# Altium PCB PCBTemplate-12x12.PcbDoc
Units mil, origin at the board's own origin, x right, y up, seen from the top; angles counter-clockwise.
Board outline 12000 x 12000 mil, 4 copper layers (Top Layer, Internal Plane 1, Internal Plane 2, Bottom Layer); 0 components, 0 nets, 1 pads, 0 vias.
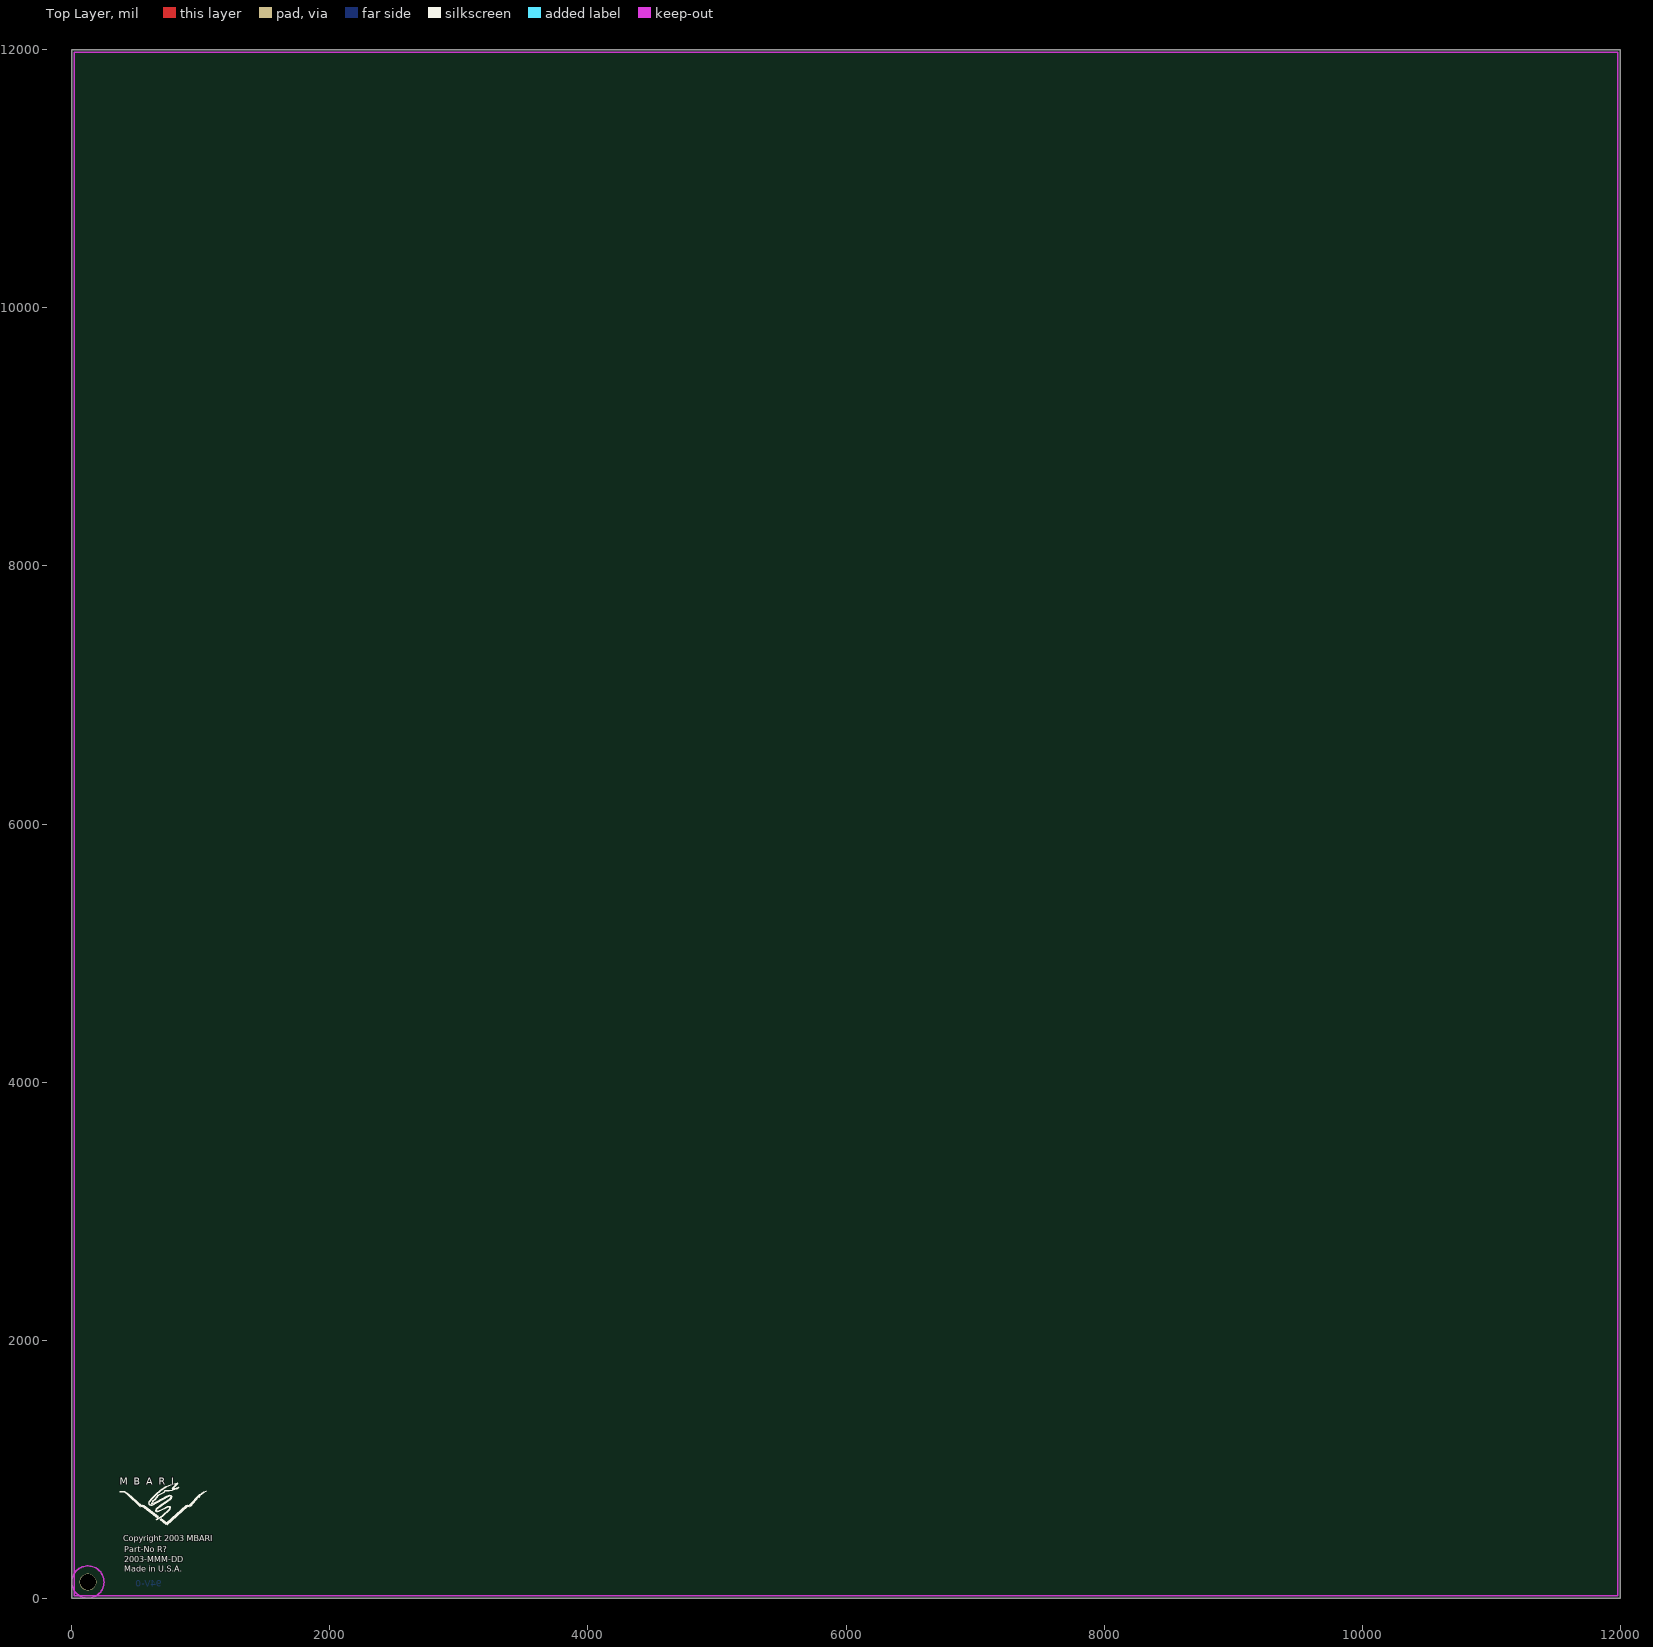
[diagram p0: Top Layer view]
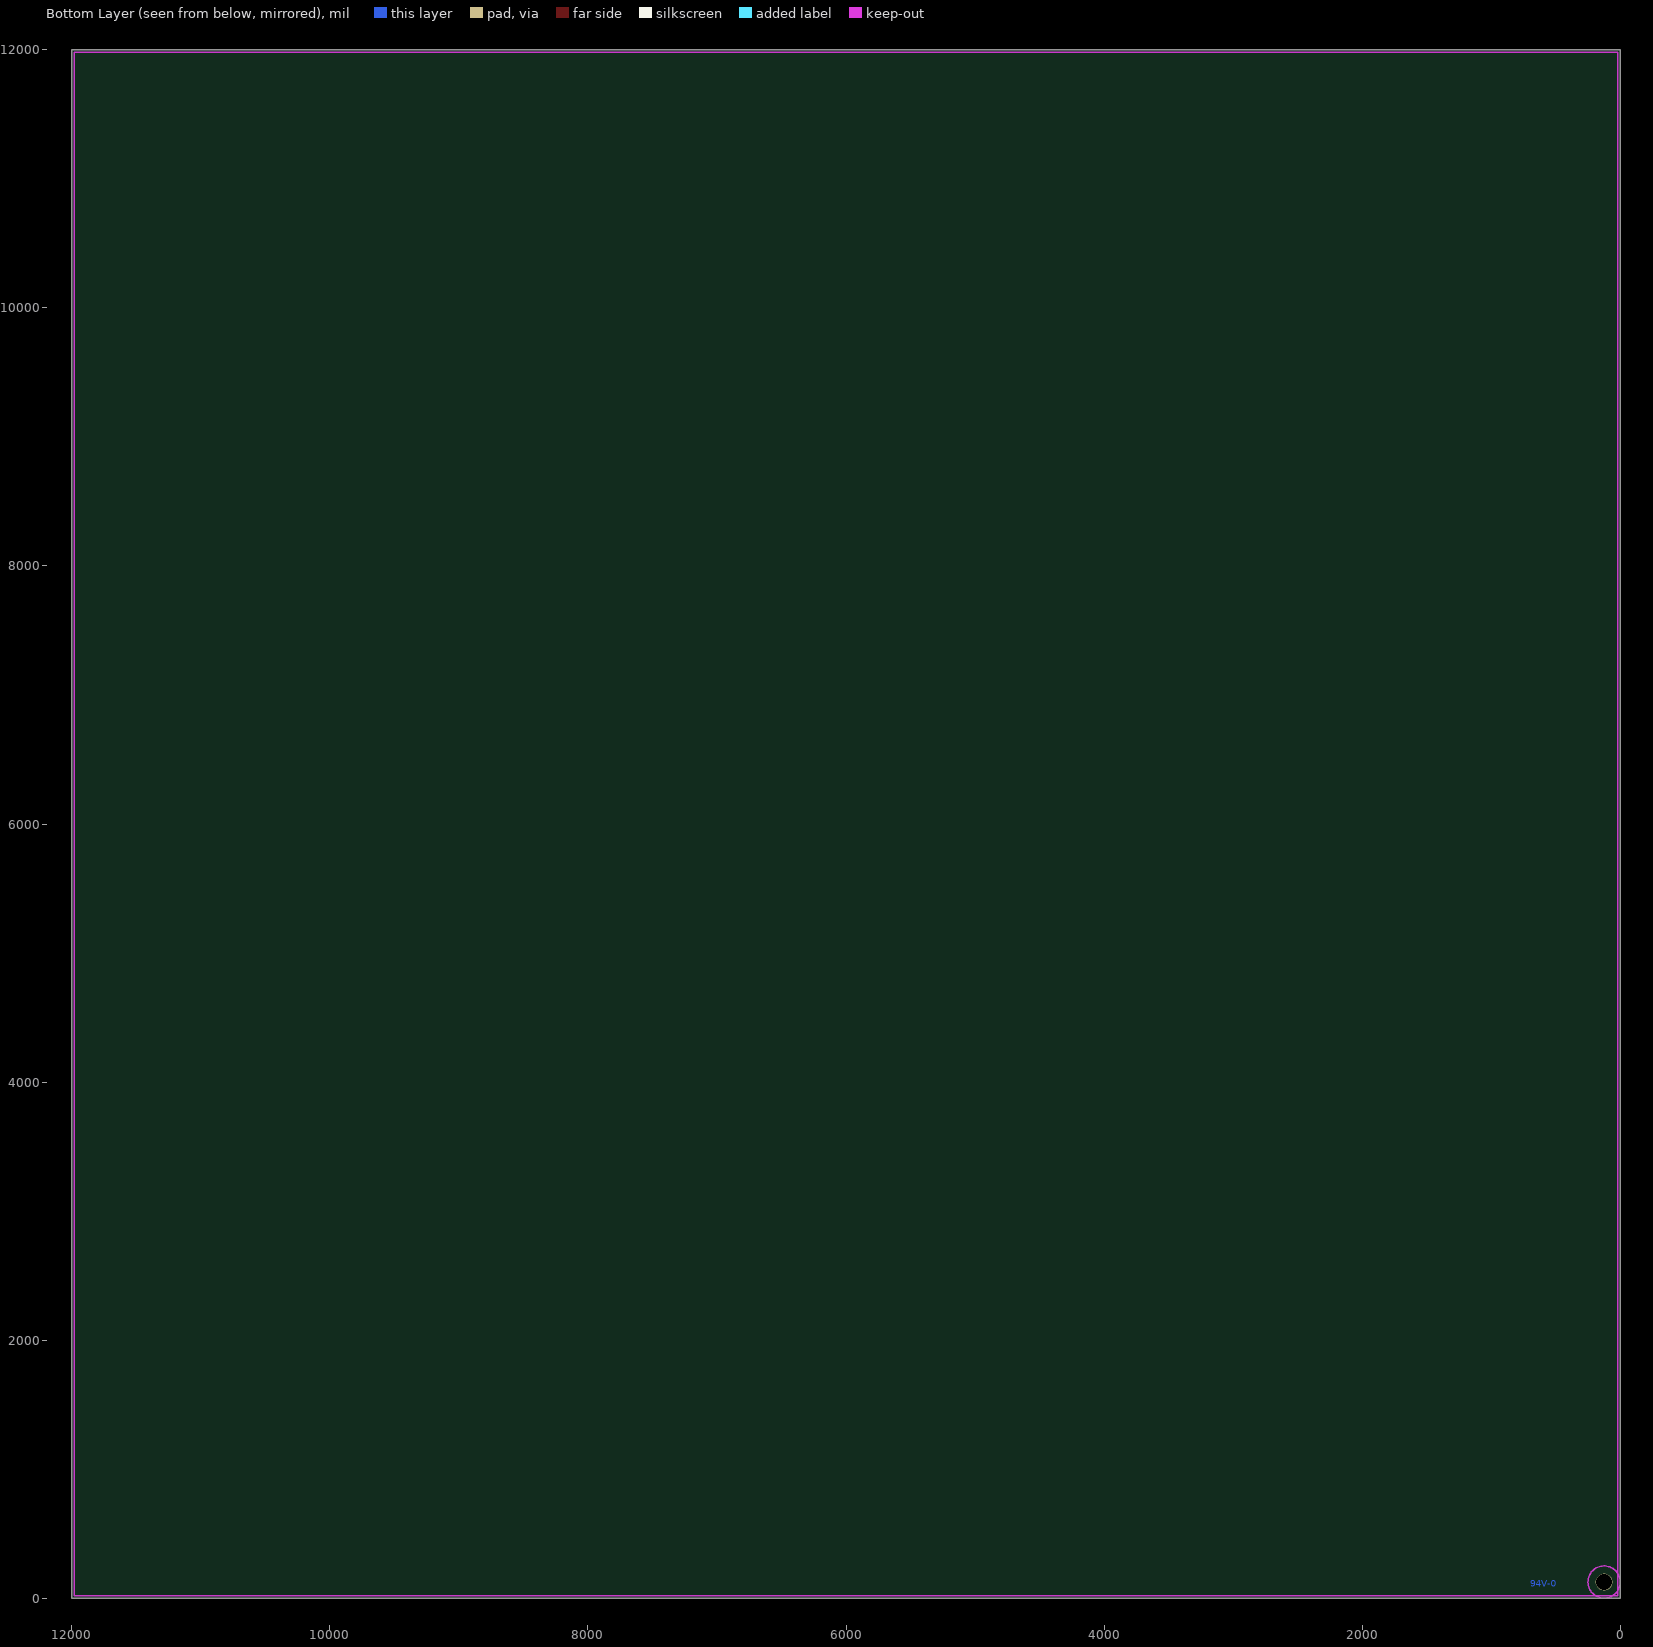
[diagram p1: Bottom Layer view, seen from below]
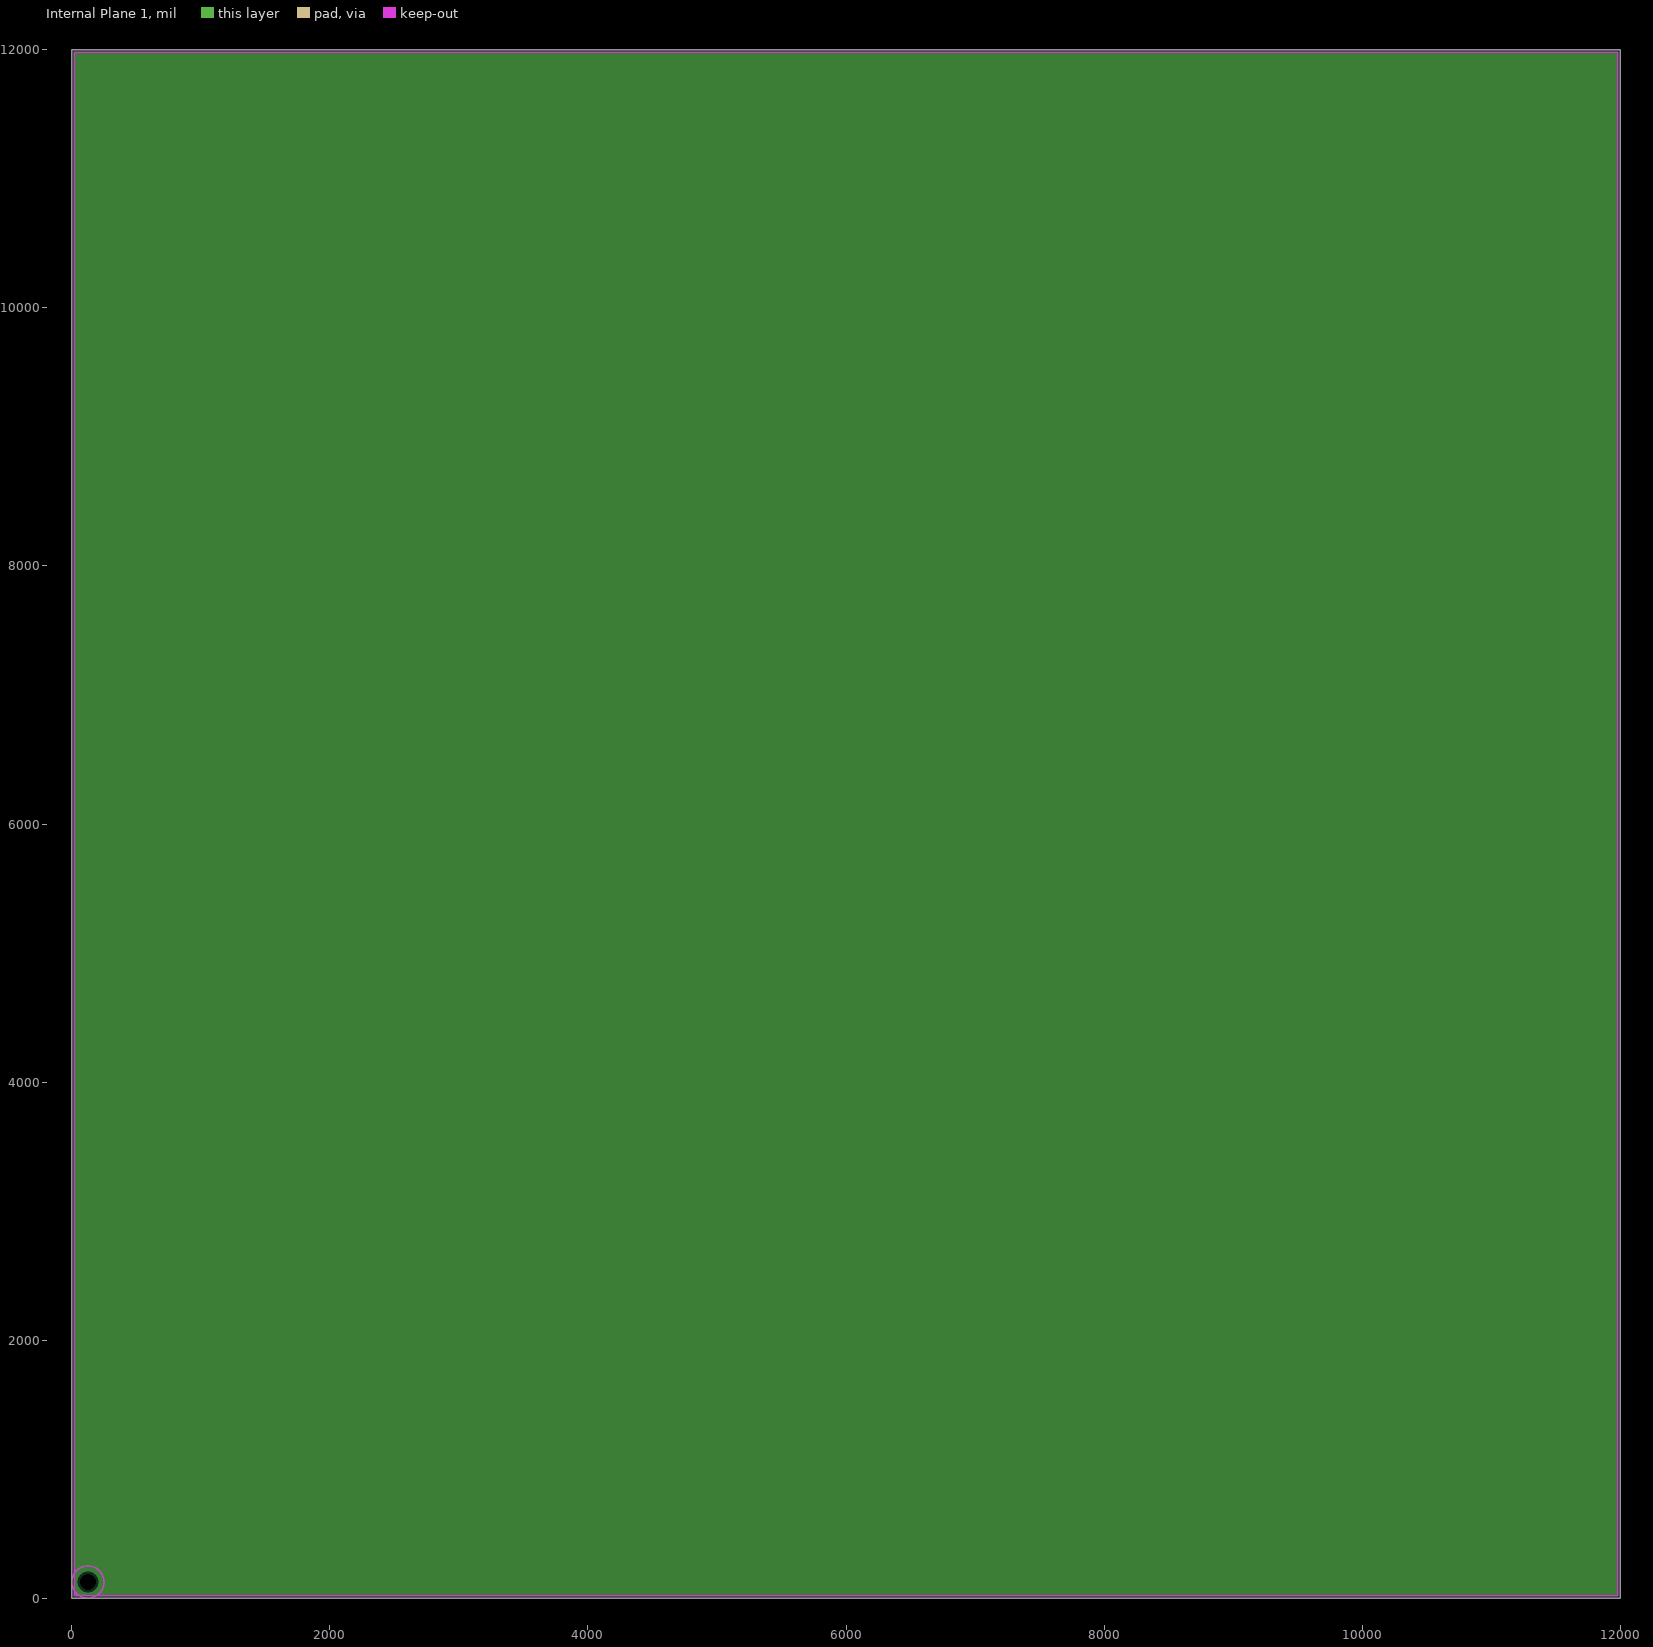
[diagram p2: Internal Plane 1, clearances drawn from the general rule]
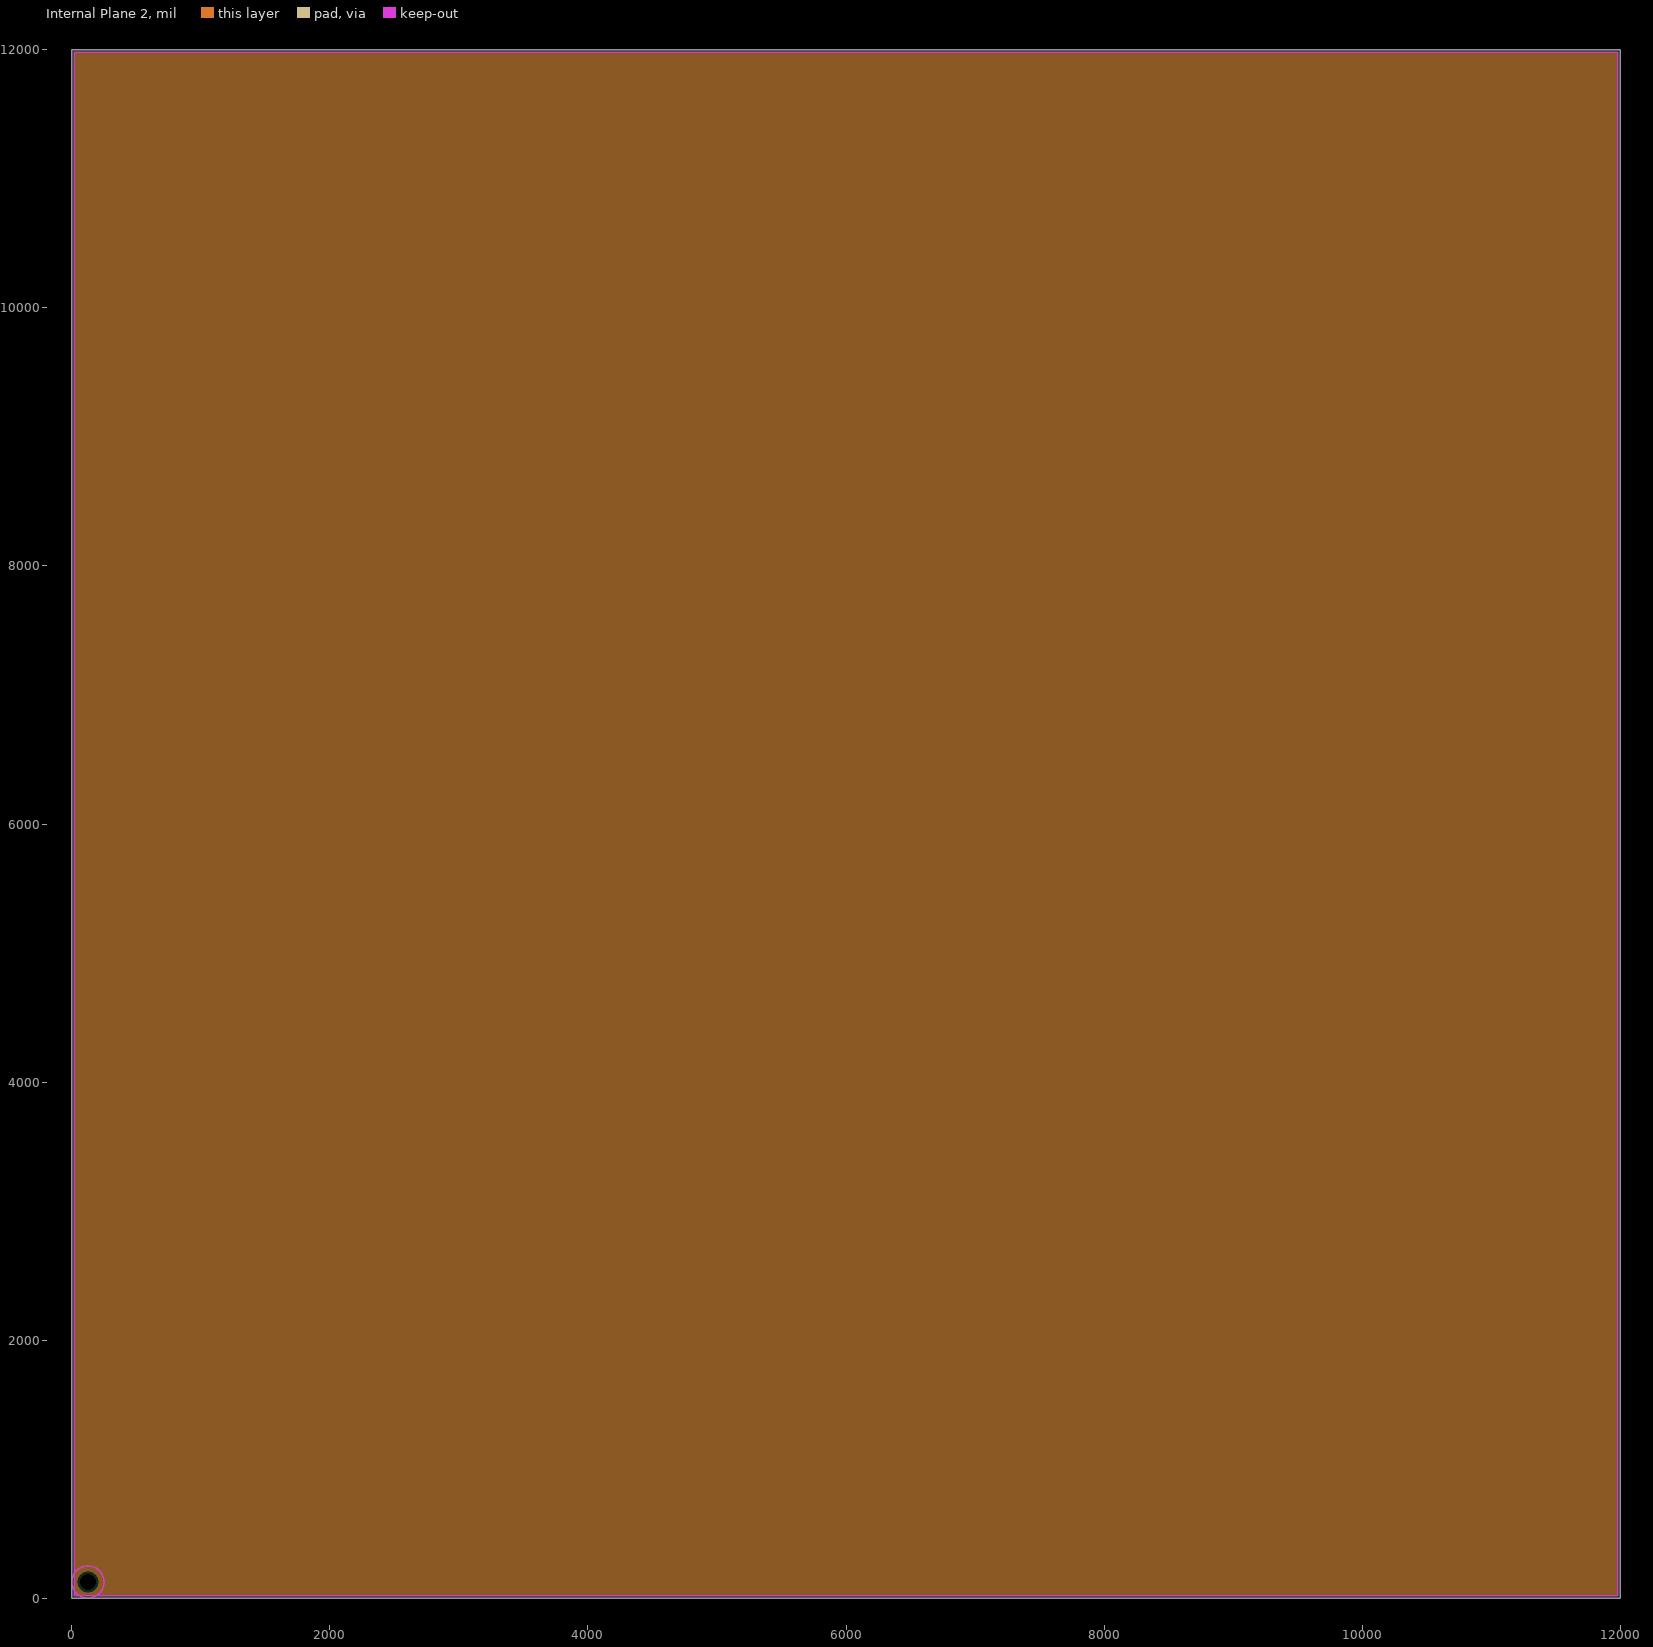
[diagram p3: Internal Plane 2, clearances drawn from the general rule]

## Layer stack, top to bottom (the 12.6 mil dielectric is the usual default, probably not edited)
Top Layer: signal copper 1.4
Dielectric: dielectric 12.6, FR-4, Dk 4.8
Internal Plane 1: plane copper 1.4
Dielectric: dielectric 12.6, FR-4, Dk 4.8
Internal Plane 2: plane copper 1.4
Dielectric: dielectric 12.6, FR-4, Dk 4.8
Bottom Layer: signal copper 1.4

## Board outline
0,0 12000,0 12000,12000 0,12000

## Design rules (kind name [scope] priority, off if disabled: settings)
Clearance [All] p1: gap=13
ComponentClearance [All] p1: gap=10 collisioncheckmode=0
FanoutControl Fanout_Small [(CompPinCount < 5)] p1: bgadir=Out bgaviamode=Centered fanoutstyle=Auto fanoutdirection=OutThenIn viagrid=1 // Fanout_Small (Default Rule)
FanoutControl Fanout_Default [All] p2: bgadir=Out bgaviamode=Centered fanoutstyle=Auto fanoutdirection=Alternating viagrid=1 // Fanout_Default (Default Rule)
FanoutControl Fanout_BGA [IsBGA] p4: bgadir=Out bgaviamode=Centered fanoutstyle=Auto fanoutdirection=Alternating viagrid=1 // Fanout_BGA (Default Rule)
FanoutControl Fanout_LCC [IsLCC] p5: bgadir=Out bgaviamode=Centered fanoutstyle=Auto fanoutdirection=Alternating viagrid=1 // Fanout_LCC (Default Rule)
HoleSize [All] p1: absolutevalues=TRUE maxlimit=152 minlimit=1 maxpercent=80.000 minpercent=20.000
PlaneClearance [All] p1: clearance=20
PlaneConnect [All] p1: planeconnectstyle=Relief reliefexpansion=20 reliefentries=4 reliefconductorwidth=10 reliefairgap=10
PolygonConnect [All] p1: connectstyle=Relief reliefconductorwidth=10 reliefentries=4 polygonreliefangle="90 Angle"
RoutingLayers [All] p1: top layer=Horizontal bottom layer=Vertical
RoutingVias [All] p1: holewidth=35 width=52 viastyle="Through Hole" minholewidth=28 minwidth=32 maxholewidth=86 maxwidth=72
SolderMaskExpansion [All] p1: expansion=4
TestPointUsage [All] p1: valid=0 allowmultiple=FALSE
Testpoint [All] p1: side=15 testpointundercomponent=TRUE minsize=40 maxsize=100 preferedsize=60 minholesize=0 maxholesize=40 preferedholesize=32 testpointgrid=1 style=1023 order=-539222988
Width [All] p1: maxlimit=250 minlimit=8 preferedwidth=12 toplayer_prefwidth=10 bottomlayer_prefwidth=10 minimp=50.000000 maximp=50.000000 favimp=50.000000
9 further rules are at their usual default settings.

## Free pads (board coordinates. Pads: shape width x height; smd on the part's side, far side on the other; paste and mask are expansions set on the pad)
  round 130 hole 125: 0(125,125)

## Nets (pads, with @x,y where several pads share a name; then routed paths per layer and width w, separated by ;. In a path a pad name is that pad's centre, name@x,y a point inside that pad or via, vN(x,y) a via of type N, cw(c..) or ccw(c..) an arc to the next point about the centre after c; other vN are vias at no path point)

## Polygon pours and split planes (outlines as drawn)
no net on Internal Plane 1 (split plane): 20.01,20.01 20.01,11979.99 11979.99,11979.99 11979.99,20.01
no net on Internal Plane 2 (split plane): 20.01,20.01 20.01,11979.99 11979.99,11979.99 11979.99,20.01

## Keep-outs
Keep-Out Layer:
  circle w10: c125,125 r125
  lines w10: 20,20 20,11980 11980,11980 11980,20 20,20
  text ".GKO" at 18240,-540 h90

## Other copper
Top Layer:
  text ".GTL" at 18240,-540 h90
Bottom Layer:
  text "94V-0" at 697.07,88.79 h50
  text ".GBL" at 18240,-540 h90

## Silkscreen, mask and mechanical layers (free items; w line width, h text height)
Top Overlay:
  lines w10: 373,826 405,824 436,806 537,715 550,719 557,718 671,631 ; 428,808 531,711 ; 536,708 551,712 666,624 ; 653,608 699,635 758,689 761,696 761,706 759,709 753,710 746,710 ; 684,610 731,573 ; 688,617 736,579 888,717 897,721 911,716 990,802 993,797 1022,823 1042,827 ; 760,695 760,703 758,707 753,709 746,710 ; 894,713 909,708 ; 916,712 981,785 ; 984,782 990,791 ; 746,710 672,672 664,670 657,672 653,679 654,685 658,693 669,701 764,766 772,775 775,782 773,787 771,791 767,793 760,793 750,790 622,720 612,719 604,724 599,728 596,735 597,741 601,749 623,774 651,801 690,835 733,863 772,881 821,889 778,850 795,850 824,855 829,859 812,849 796,844 780,838 757,833 722,833 715,822 702,814 687,807 669,797 647,767 629,752 618,737 622,733 652,743 700,771 736,791 760,797 766,795 770,784 759,768 691,721 653,689 652,677 656,672 679,676 696,687 739,707 746,710 ; 737,568 896,713 737,568
  text "M  B  A  R  I" at 370,880 h55
  text "Copyright 2003 MBARI" at 400,440 h45
  text "Part-No R?" at 405,356.68 h45
  text "2003-MMM-DD" at 405,276.68 h45
  text "Made in U.S.A." at 405,206.68 h45
  text ".GTO" at 18240,-540 h90
Bottom Overlay:
  text ".GBO" at 18250,-540 h90
Top Solder:
  text ".GTS" at 18240,-540 h90
Bottom Solder:
  text ".GBS" at 18240,-540 h90
Drill Guide:
  text ".GG1" at 15450,-540 h90
Mechanical 4:
  the board outline again, w10
Mechanical 16:
  lines w5: -800,1800 -600,1800 ; -800,4200 -600,4200 ; -800,6600 -600,6600 ; -800,9000 -600,9000 ; -800,11400 -600,11400 ; 1600,-800 1600,-600 ; 1600,13600 1600,13800 ; 4000,-800 4000,-600 ; 4000,13600 4000,13800 ; 6400,-800 6400,-600 ; 6400,13600 6400,13800 ; 8800,-800 8800,-600 ; 8800,13600 8800,13800 ; 11100,-600 18600,-600 ; 11200,-800 11200,-600 ; 11200,13600 11200,13800 ; 12700,0 18600,0 ; 13600,-800 13600,-600 ; 13600,13600 13600,13800 ; 14100,-300 18600,-300 ; 14100,300 15600,300 ; 15600,-600 15600,0 15600,600 ; 16000,-800 16000,-600 ; 16000,13600 16000,13800 ; 17700,-600 17700,0 ; 18600,600 15600,600 ; 18600,1800 18800,1800 ; 18600,4200 18800,4200 ; 18600,6600 18800,6600 ; 18600,9000 18800,9000 ; 18600,11400 18800,11400 ; 14100,600 14100,-600 12700,-600 12700,600 14100,600 ; 14100,600 15600,600 ; 18600,-600 18600,13600 -600,13600 -600,-600 18600,-600 ; -800,-800 18800,-800 18800,13800 -800,13800 -800,-800
  lines w10: 13033,446 13065,444 13096,426 13197,335 13210,339 13217,338 13331,251 ; 13088,428 13191,331 ; 13196,328 13211,332 13326,244 ; 13313,228 13359,255 13418,309 13421,316 13421,326 13419,329 13413,330 13406,330 ; 13344,230 13391,193 ; 13348,237 13396,199 13548,337 13557,341 13571,336 13650,422 13653,417 13682,443 13702,447 ; 13420,315 13420,323 13418,327 13413,329 13406,330 ; 13554,333 13569,328 ; 13576,332 13641,405 ; 13644,402 13650,411 ; 13406,330 13332,292 13324,290 13317,292 13313,299 13314,305 13318,313 13329,321 13424,386 13432,395 13435,402 13433,407 13431,411 13427,413 13420,413 13410,410 13282,340 13272,339 13264,344 13259,348 13256,355 13257,361 13261,369 13283,394 13311,421 13350,455 13393,483 13432,501 13481,509 13438,470 13455,470 13484,475 13489,479 13472,469 13456,464 13440,458 13417,453 13382,453 13375,442 13362,434 13347,427 13329,417 13307,387 13289,372 13278,357 13282,353 13312,363 13360,391 13396,411 13420,417 13426,415 13430,404 13419,388 13351,341 13313,309 13312,297 13316,292 13339,296 13356,307 13399,327 13406,330 ; 13397,188 13556,333 13397,188
  text "7" at 14870,13670 h70
  text "8" at 17240,13670 h70
  text "1" at 520,13660 h70
  text "2" at 2800,13660 h70
  text "3" at 5160,13660 h70
  text "4" at 7510,13660 h70
  text "5" at 9970,13660 h70
  text "6" at 12340,13660 h70
  text "A" at -730,12540 h70
  text "A" at 18670,12540 h70
  text "B" at -740,10130 h70
  text "B" at 18660,10130 h70
  text "C" at -720,7860 h70
  text "C" at 18680,7860 h70
  text "D" at -740,5410 h70
  text "D" at 18660,5410 h70
  text "E" at -720,2900 h70
  text "E" at 18680,2900 h70
  text "M  B  A  R  I" at 13030,500 h55
  text "ENGINEER:" at 14150,500 h45
  text "TITLE:" at 15650,500 h45
  text "Mark Sibenac" at 14660,470 h70
  text "F" at -740,450 h70
  text "F" at 18660,450 h70
  text "Title I" at 16000,380 h90
  text "1 831 775 2028" at 14650,330 h60
  text "PCB DESIGNER:" at 14150,205 h45
  text "Title II" at 16020,160 h90
  text "Copyright      2003" at 12880,150 h60
  text "Monterey Bay Aquarium Research Institute" at 12750,40 h45
  text "DATE:" at 14150,-100 h45
  text "PART NO.:" at 15650,-100 h45
  text "REV:" at 17750,-100 h45
  text ".PRINT_DATE" at 14200,-220 h70
  text "1" at 18030,-220 h90
  text "Part Number" at 16010,-230 h60
  text "M.B.A.R.I." at 12780,-240 h100
  text "7700 Sandholdt Rd." at 12770,-340 h60
  text "FILE NAME:" at 14150,-400 h45
  text "DWG NO:" at 15650,-400 h45
  text "GERBER:" at 17750,-400 h45
  text "Moss Landing, CA 95039" at 12770,-450 h60
  text "DWG Number" at 16010,-490 h60
  text ".PCB_FILE_NAME_NO_PATH" at 14200,-520 h70
  text ".GM16" at 17860,-530 h70
  text "Fax: 1 831 775 1646" at 12770,-550 h60
  text "7" at 14870,-730 h70
  text "8" at 17240,-730 h70
  text "1" at 520,-740 h70
  text "2" at 2800,-740 h70
  text "3" at 5160,-740 h70
  text "4" at 7510,-740 h70
  text "5" at 9970,-740 h70
  text "6" at 12340,-740 h70
Drill Drawing:
  text ".LEGEND" at 9945,870 h60
  text "Drill Drawing." at 9925,780 h60
  text ".GD1" at 15445,-540 h90

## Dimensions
125,125 to 0,0 on Mechanical 4
125,125 to 0,0 on Mechanical 4
0,12000 to 0,0 on Mechanical 4
0,0 to 12000,0 on Mechanical 4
